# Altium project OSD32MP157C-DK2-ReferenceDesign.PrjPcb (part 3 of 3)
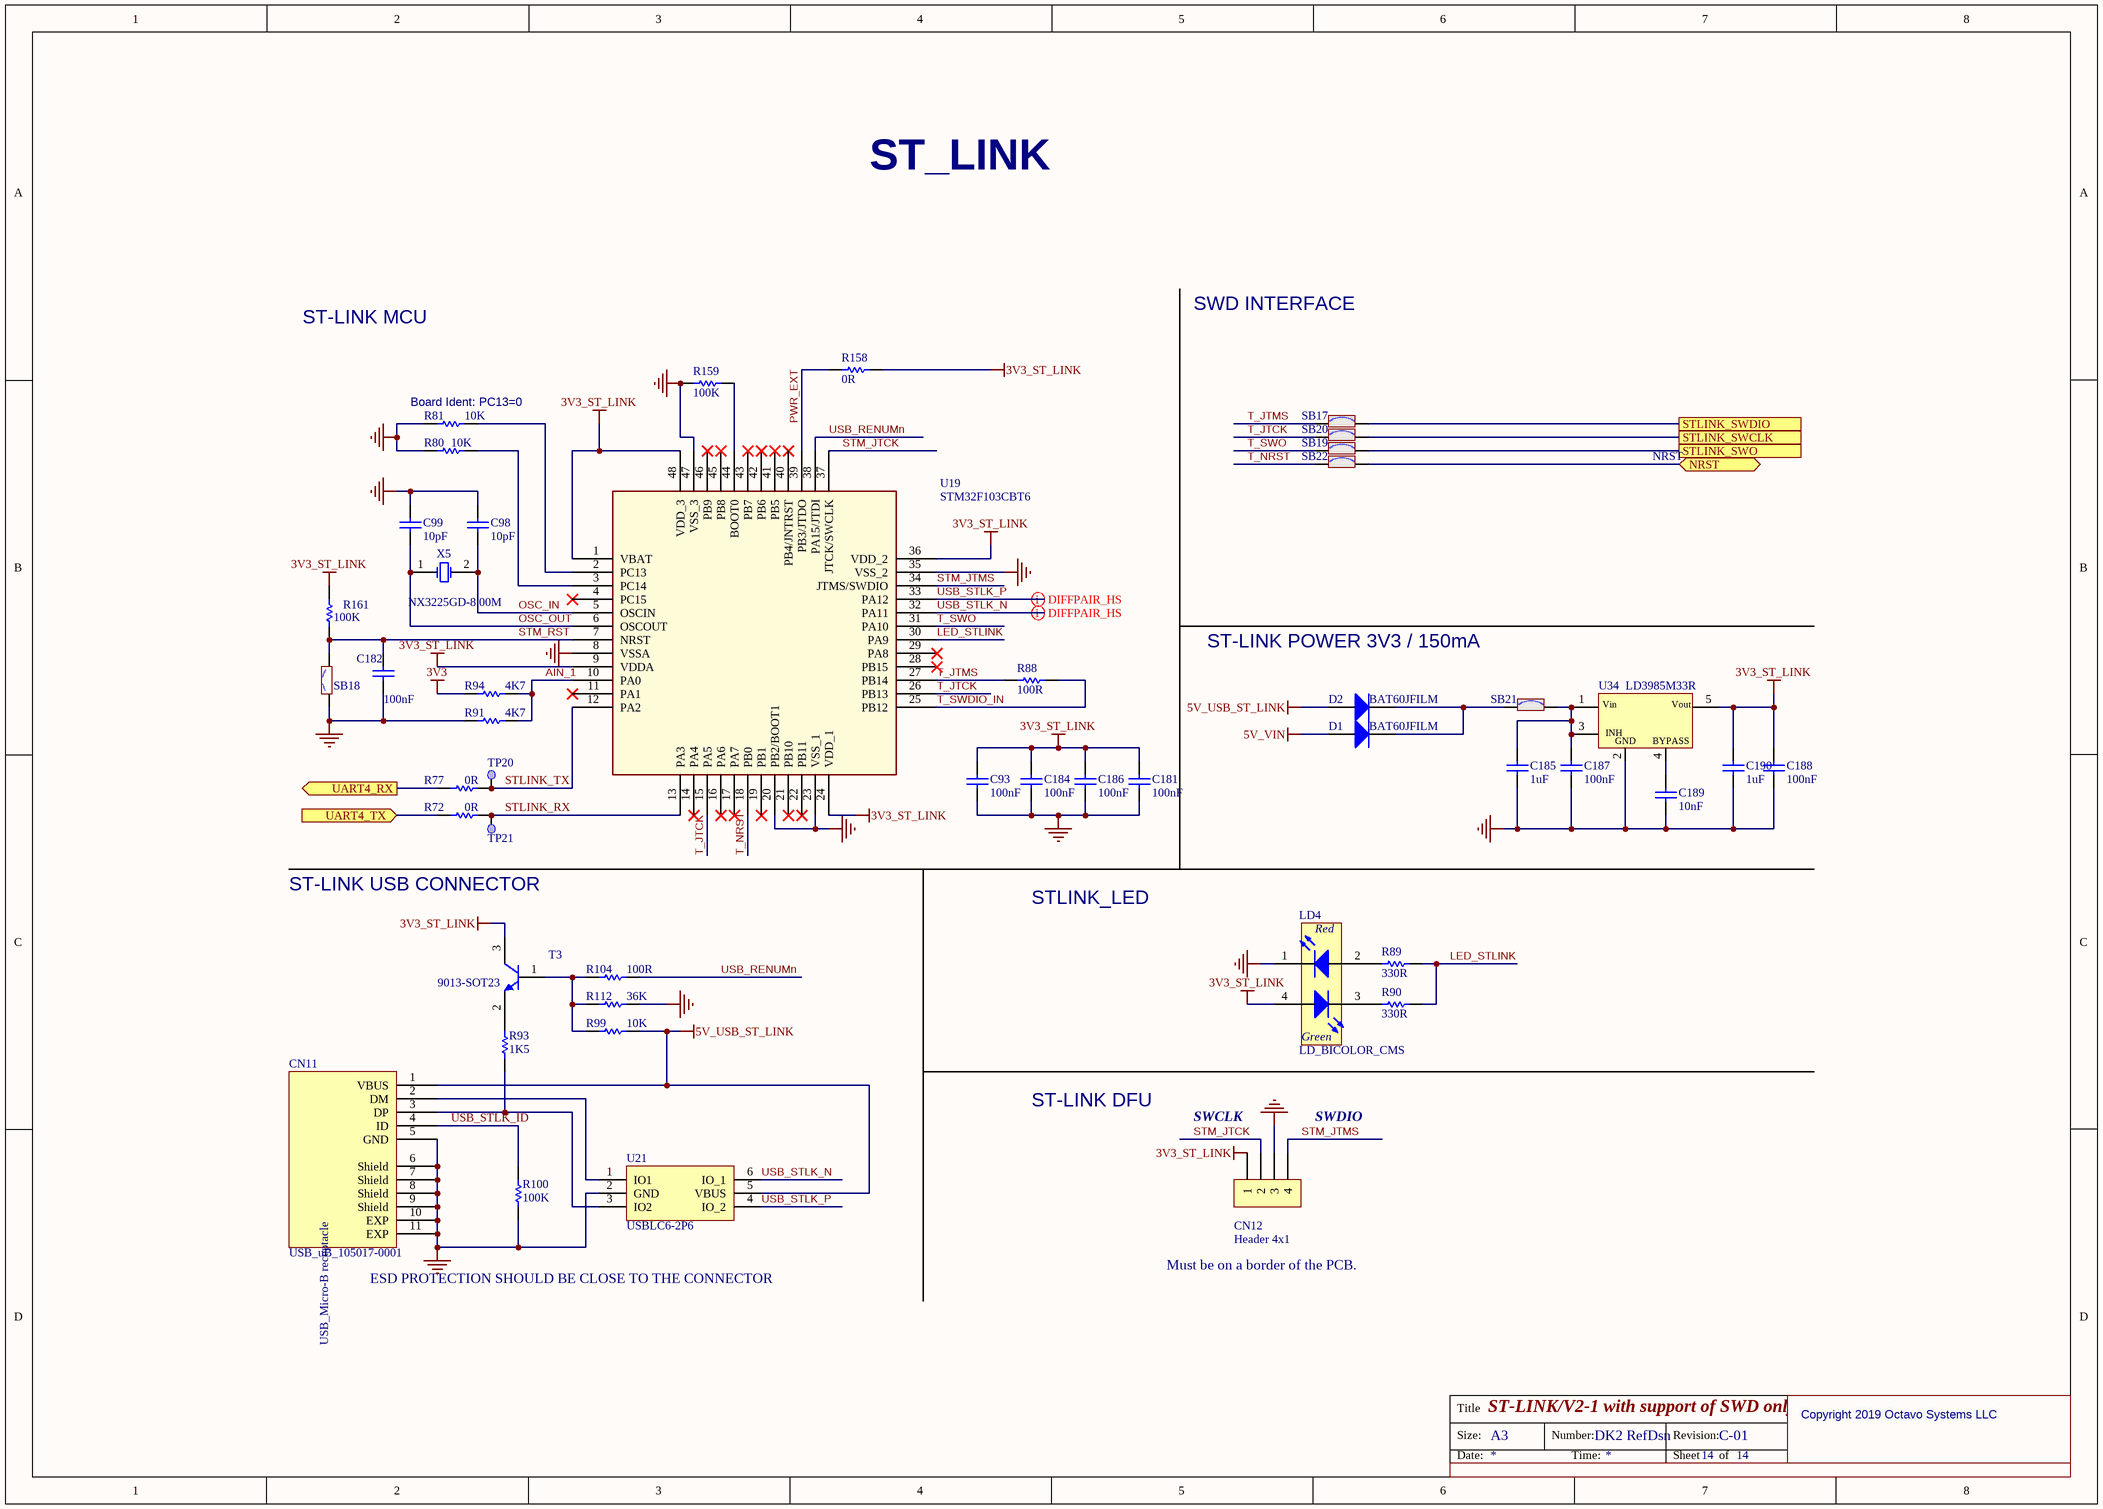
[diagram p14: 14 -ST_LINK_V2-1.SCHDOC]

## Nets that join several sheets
1V2_HDMI: 3 - Power_MPU (U13.H4), 8 - HDMI (5 pins)
1V8_AUDIO: 3 - Power_MPU (U13.J4), 6 - AUDIO (8 pins)
3V3: 2 - OSD32MP157C_18x18 (6 pins), 3 - Power_MPU (U13.H3 U13.J3), 5 - USB_Host_Hub&TypeC_DRP (18 pins), 6 - AUDIO (SB5.1), 7 - DSI_LCD (L7.1 R11.1), 9 - GPIO_&_Arduino_ Connectors (5 pins), 11 - Ethernet (L10.2 L11.2), 12 -  Peripherals (10 pins), 13 - WLAN_BLUETOOTH (10 pins), 14 -ST_LINK_V2-1 (R94.1)
3V3_HDMI: 3 - Power_MPU (U13.G4), 8 - HDMI (R154.2)
5V_VIN: 3 - Power_MPU (7 pins), 4 - PMIC (6 pins), 5 - USB_Host_Hub&TypeC_DRP (9 pins), 8 - HDMI (F1.1 R97.2 R98.2), 9 - GPIO_&_Arduino_ Connectors (CN2.2 CN2.4 R165.1 U23.1), 14 -ST_LINK_V2-1 (D1.1)
GND: 2 - OSD32MP157C_18x18 (9 pins), 3 - Power_MPU (72 pins), 4 - PMIC (20 pins), 5 - USB_Host_Hub&TypeC_DRP (74 pins), 6 - AUDIO (8 pins), 7 - DSI_LCD (18 pins), 8 - HDMI (36 pins), 9 - GPIO_&_Arduino_ Connectors (15 pins), 11 - Ethernet (34 pins), 12 -  Peripherals (20 pins), 13 - WLAN_BLUETOOTH (22 pins), 14 -ST_LINK_V2-1 (35 pins)
VDD: 2 - OSD32MP157C_18x18 (R5.1 R7.1), 3 - Power_MPU (10 pins), 12 -  Peripherals (R101.2 R102.2 R109.2)
VREF+: 3 - Power_MPU (R78.2 R79.2 U13.M2), 9 - GPIO_&_Arduino_ Connectors (C1.2 R4.2)
ARD_A0: 2 - OSD32MP157C_18x18 (U13.L1), 9 - GPIO_&_Arduino_ Connectors (CN17.1)
ARD_A1: 2 - OSD32MP157C_18x18 (U13.L2), 9 - GPIO_&_Arduino_ Connectors (CN17.2)
ARD_A2: 2 - OSD32MP157C_18x18 (U13.B10), 9 - GPIO_&_Arduino_ Connectors (CN17.3)
ARD_A3: 2 - OSD32MP157C_18x18 (U13.A10), 9 - GPIO_&_Arduino_ Connectors (CN17.4)
ARD_A4: 2 - OSD32MP157C_18x18 (U13.B6), 9 - GPIO_&_Arduino_ Connectors (SB24.1)
ARD_A5: 2 - OSD32MP157C_18x18 (U13.C11), 9 - GPIO_&_Arduino_ Connectors (SB26.1)
ARD_D0: 2 - OSD32MP157C_18x18 (U13.D17), 9 - GPIO_&_Arduino_ Connectors (CN14.1)
ARD_D1: 2 - OSD32MP157C_18x18 (U13.D18), 9 - GPIO_&_Arduino_ Connectors (CN14.2)
ARD_D2: 2 - OSD32MP157C_18x18 (U13.T7), 9 - GPIO_&_Arduino_ Connectors (CN14.3)
ARD_D3: 2 - OSD32MP157C_18x18 (U13.C3), 9 - GPIO_&_Arduino_ Connectors (CN14.4)
ARD_D4: 2 - OSD32MP157C_18x18 (U13.E17), 9 - GPIO_&_Arduino_ Connectors (CN14.5)
ARD_D5: 2 - OSD32MP157C_18x18 (U13.A2), 9 - GPIO_&_Arduino_ Connectors (CN14.6)
ARD_D6: 2 - OSD32MP157C_18x18 (U13.E16), 9 - GPIO_&_Arduino_ Connectors (CN14.7)
ARD_D7: 2 - OSD32MP157C_18x18 (U13.U11), 9 - GPIO_&_Arduino_ Connectors (CN14.8)
ARD_D8: 2 - OSD32MP157C_18x18 (U13.C9), 9 - GPIO_&_Arduino_ Connectors (CN13.1)
ARD_D9: 2 - OSD32MP157C_18x18 (U13.B5), 9 - GPIO_&_Arduino_ Connectors (CN13.2)
ARD_D10: 2 - OSD32MP157C_18x18 (U13.V5), 9 - GPIO_&_Arduino_ Connectors (CN13.3)
ARD_D11: 2 - OSD32MP157C_18x18 (U13.V4), 9 - GPIO_&_Arduino_ Connectors (CN13.4)
ARD_D12: 2 - OSD32MP157C_18x18 (U13.T5), 9 - GPIO_&_Arduino_ Connectors (CN13.5)
ARD_D13: 2 - OSD32MP157C_18x18 (U13.U5), 9 - GPIO_&_Arduino_ Connectors (CN13.6 SB6.1)
ARD_D14: 2 - OSD32MP157C_18x18 (R166.2 U13.L18), 9 - GPIO_&_Arduino_ Connectors (CN2.3 CN13.9 SB23.1)
ARD_D15: 2 - OSD32MP157C_18x18 (R167.2 U13.L17), 9 - GPIO_&_Arduino_ Connectors (CN2.5 CN13.10 SB25.1)
AUDIO_RST: 2 - OSD32MP157C_18x18 (U13.M17), 6 - AUDIO (R84.2 U20.25)
BOOT0: 2 - OSD32MP157C_18x18 (U13.J6), 12 -  Peripherals (SW1.1)
BOOT1: 2 - OSD32MP157C_18x18 (U13.H6), 12 -  Peripherals (R82.2)
BOOT2: 2 - OSD32MP157C_18x18 (U13.G6), 12 -  Peripherals (SW1.2)
BT_DEV_WAKE: 2 - OSD32MP157C_18x18 (U13.D2), 13 - WLAN_BLUETOOTH (U8.39)
BT_HOST_WAKE: 2 - OSD32MP157C_18x18 (U13.T6), 13 - WLAN_BLUETOOTH (U8.38)
BT_PCM_CLK: 2 - OSD32MP157C_18x18 (U13.F1), 13 - WLAN_BLUETOOTH (U8.11)
BT_PCM_SDI: 2 - OSD32MP157C_18x18 (U13.F2), 13 - WLAN_BLUETOOTH (U8.10)
BT_PCM_SDO: 2 - OSD32MP157C_18x18 (U13.F3), 13 - WLAN_BLUETOOTH (U8.9)
BT_PCM_WS: 2 - OSD32MP157C_18x18 (U13.E1), 13 - WLAN_BLUETOOTH (U8.8)
BT_REG_ON: 2 - OSD32MP157C_18x18 (U13.D1), 13 - WLAN_BLUETOOTH (TP29.1 U8.14)
DSI_CK_N: 2 - OSD32MP157C_18x18 (U13.P16), 7 - DSI_LCD (CN4.9 CN4.10)
DSI_CK_P: 2 - OSD32MP157C_18x18 (U13.N16), 7 - DSI_LCD (CN4.11 CN4.12)
DSI_D0_N: 2 - OSD32MP157C_18x18 (U13.P18), 7 - DSI_LCD (CN4.15 CN4.16)
DSI_D0_P: 2 - OSD32MP157C_18x18 (U13.P17), 7 - DSI_LCD (CN4.17 CN4.18)
DSI_D1_N: 2 - OSD32MP157C_18x18 (U13.N18), 7 - DSI_LCD (CN4.3 CN4.4)
DSI_D1_P: 2 - OSD32MP157C_18x18 (U13.N17), 7 - DSI_LCD (CN4.5 CN4.6)
DSI_LCD_BL_CTRL: 2 - OSD32MP157C_18x18 (U13.T15), 7 - DSI_LCD (CN4.37 CN4.38)
DSI_LCD_INT: 2 - OSD32MP157C_18x18 (U13.T18), 7 - DSI_LCD (CN4.33 CN4.34)
DSI_RESET: 2 - OSD32MP157C_18x18 (U13.R17), 7 - DSI_LCD (CN4.39 CN4.40 R11.2)
DSI_TE: 2 - OSD32MP157C_18x18 (U13.R18), 7 - DSI_LCD (CN4.35 CN4.36)
ETH_CLK: 2 - OSD32MP157C_18x18 (U13.C17), 11 - Ethernet (R69.2)
ETH_CLK125: 2 - OSD32MP157C_18x18 (U13.C15), 11 - Ethernet (R153.1)
ETH_GTX_CLK: 2 - OSD32MP157C_18x18 (U13.B9), 11 - Ethernet (U18.20)
ETH_MDC: 2 - OSD32MP157C_18x18 (U13.B15), 11 - Ethernet (R76.1 U18.13)
ETH_MDINT: 2 - OSD32MP157C_18x18 (U13.B17), 11 - Ethernet (R65.1 U18.31)
ETH_MDIO: 2 - OSD32MP157C_18x18 (U13.A15), 11 - Ethernet (R75.1 U18.14)
ETH_NRST: 2 - OSD32MP157C_18x18 (R300.2 U13.C8), 11 - Ethernet (U18.12)
ETH_RX_CLK: 2 - OSD32MP157C_18x18 (U13.C16), 11 - Ethernet (R50.2 R58.1)
ETH_RX_DV: 2 - OSD32MP157C_18x18 (U13.A12), 11 - Ethernet (R51.2 R59.1)
ETH_RXD0: 2 - OSD32MP157C_18x18 (U13.B12), 11 - Ethernet (R52.1 R60.1)
ETH_RXD1: 2 - OSD32MP157C_18x18 (U13.C12), 11 - Ethernet (R53.1 R61.1)
ETH_RXD2: 2 - OSD32MP157C_18x18 (U13.A11), 11 - Ethernet (R54.2 R62.1)
ETH_RXD3: 2 - OSD32MP157C_18x18 (U13.B11), 11 - Ethernet (R55.1 R63.1)
ETH_TX_EN: 2 - OSD32MP157C_18x18 (U13.A9), 11 - Ethernet (U18.19)
ETH_TXD0: 2 - OSD32MP157C_18x18 (U13.B7), 11 - Ethernet (U18.18)
ETH_TXD1: 2 - OSD32MP157C_18x18 (U13.A7), 11 - Ethernet (U18.17)
ETH_TXD2: 2 - OSD32MP157C_18x18 (U13.C7), 11 - Ethernet (U18.16)
ETH_TXD3: 2 - OSD32MP157C_18x18 (U13.A6), 11 - Ethernet (U18.15)
EXP_GPIO4: 2 - OSD32MP157C_18x18 (TP19.1 U13.T17), 9 - GPIO_&_Arduino_ Connectors (CN2.7)
EXP_GPIO5: 2 - OSD32MP157C_18x18 (TP1.1 U13.A8), 9 - GPIO_&_Arduino_ Connectors (CN2.29)
EXP_GPIO6: 2 - OSD32MP157C_18x18 (U13.V2), 9 - GPIO_&_Arduino_ Connectors (CN2.31)
EXP_GPIO7: 2 - OSD32MP157C_18x18 (U13.C6), 9 - GPIO_&_Arduino_ Connectors (CN2.26)
EXP_GPIO8: 2 - OSD32MP157C_18x18 (U13.F18), 9 - GPIO_&_Arduino_ Connectors (CN2.24)
EXP_GPIO9: 2 - OSD32MP157C_18x18 (U13.G17), 9 - GPIO_&_Arduino_ Connectors (CN2.21)
EXP_GPIO10: 2 - OSD32MP157C_18x18 (U13.G18), 9 - GPIO_&_Arduino_ Connectors (CN2.19)
EXP_GPIO11: 2 - OSD32MP157C_18x18 (U13.G16), 9 - GPIO_&_Arduino_ Connectors (CN2.23)
EXP_GPIO12: 2 - OSD32MP157C_18x18 (U13.F17), 9 - GPIO_&_Arduino_ Connectors (CN2.32)
EXP_GPIO13: 2 - OSD32MP157C_18x18 (U13.R16), 9 - GPIO_&_Arduino_ Connectors (CN2.33)
EXP_GPIO14: 2 - OSD32MP157C_18x18 (U13.A13), 9 - GPIO_&_Arduino_ Connectors (CN2.8)
EXP_GPIO15: 2 - OSD32MP157C_18x18 (U13.B14), 9 - GPIO_&_Arduino_ Connectors (CN2.10)
EXP_GPIO16: 2 - OSD32MP157C_18x18 (U13.A14), 9 - GPIO_&_Arduino_ Connectors (CN2.36)
EXP_GPIO17: 2 - OSD32MP157C_18x18 (U13.D16), 9 - GPIO_&_Arduino_ Connectors (CN2.11)
EXP_GPIO18: 2 - OSD32MP157C_18x18 (SB14.1), 9 - GPIO_&_Arduino_ Connectors (CN2.12)
EXP_GPIO19: 2 - OSD32MP157C_18x18 (SB16.1), 9 - GPIO_&_Arduino_ Connectors (CN2.35)
EXP_GPIO20: 2 - OSD32MP157C_18x18 (SB15.1), 9 - GPIO_&_Arduino_ Connectors (CN2.38)
EXP_GPIO21: 2 - OSD32MP157C_18x18 (SB13.1), 9 - GPIO_&_Arduino_ Connectors (CN2.40)
EXP_GPIO22: 2 - OSD32MP157C_18x18 (U13.V9), 9 - GPIO_&_Arduino_ Connectors (CN2.15)
EXP_GPIO23: 2 - OSD32MP157C_18x18 (U13.V8), 9 - GPIO_&_Arduino_ Connectors (CN2.16)
EXP_GPIO24: 2 - OSD32MP157C_18x18 (U13.U8), 9 - GPIO_&_Arduino_ Connectors (CN2.18)
EXP_GPIO25: 2 - OSD32MP157C_18x18 (U13.V7), 9 - GPIO_&_Arduino_ Connectors (CN2.22)
EXP_GPIO26: 2 - OSD32MP157C_18x18 (U13.T8), 9 - GPIO_&_Arduino_ Connectors (CN2.37)
EXP_GPIO27: 2 - OSD32MP157C_18x18 (U13.U9), 9 - GPIO_&_Arduino_ Connectors (CN2.13)
HDMI_CEC: 2 - OSD32MP157C_18x18 (U13.H18), 8 - HDMI (U14.50)
HDMI_INT: 2 - OSD32MP157C_18x18 (U13.B8), 8 - HDMI (U14.52)
HDMI_NRST: 2 - OSD32MP157C_18x18 (R40.2 U13.L16), 8 - HDMI (U14.51)
I2C1_SCL: 2 - OSD32MP157C_18x18 (R1.2 U13.F16), 5 - USB_Host_Hub&TypeC_DRP (SB8.1), 6 - AUDIO (R85.2), 7 - DSI_LCD (CN4.21 CN4.22), 8 - HDMI (U14.1), 9 - GPIO_&_Arduino_ Connectors (CN2.28)
I2C1_SDA: 2 - OSD32MP157C_18x18 (R2.2 U13.C10), 5 - USB_Host_Hub&TypeC_DRP (SB7.1), 6 - AUDIO (R86.2), 7 - DSI_LCD (CN4.23 CN4.24), 8 - HDMI (U14.2), 9 - GPIO_&_Arduino_ Connectors (CN2.27)
I2C4_SCL: 2 - OSD32MP157C_18x18 (R5.2 U13.E2), 5 - USB_Host_Hub&TypeC_DRP (U12.7)
I2C4_SDA: 2 - OSD32MP157C_18x18 (R7.2 U13.E3), 5 - USB_Host_Hub&TypeC_DRP (U12.8)
I2S2_CK: 2 - OSD32MP157C_18x18 (U13.U12), 8 - HDMI (U14.45)
I2S2_SDO: 2 - OSD32MP157C_18x18 (U13.R3), 8 - HDMI (U14.41)
I2S2_WS: 2 - OSD32MP157C_18x18 (U13.U13), 8 - HDMI (U14.44)
JTDO_TRACESWO: 2 - OSD32MP157C_18x18 (TP8.1 U13.R12), 14 -ST_LINK_V2-1 (SB19.2)
LED_B: 2 - OSD32MP157C_18x18 (U13.E18), 12 -  Peripherals (R108.1)
LED_Y: 2 - OSD32MP157C_18x18 (U13.C5), 12 -  Peripherals (R107.1)
LPO_32: 2 - OSD32MP157C_18x18 (U13.C1), 13 - WLAN_BLUETOOTH (TP26.1 U8.37)
LTDC_B0: 2 - OSD32MP157C_18x18 (U13.B1), 8 - HDMI (U14.32)
LTDC_B1: 2 - OSD32MP157C_18x18 (U13.A4), 8 - HDMI (U14.31)
LTDC_B2: 2 - OSD32MP157C_18x18 (U13.C18), 8 - HDMI (U14.30)
LTDC_B3: 2 - OSD32MP157C_18x18 (U13.V6), 8 - HDMI (U14.29)
LTDC_B4: 2 - OSD32MP157C_18x18 (U13.P1), 8 - HDMI (U14.28)
LTDC_B5: 2 - OSD32MP157C_18x18 (U13.A5), 8 - HDMI (U14.27)
LTDC_B6: 2 - OSD32MP157C_18x18 (U13.T13), 8 - HDMI (U14.25)
LTDC_B7: 2 - OSD32MP157C_18x18 (U13.B2), 8 - HDMI (U14.24)
LTDC_CLK: 2 - OSD32MP157C_18x18 (U13.H17), 8 - HDMI (U14.22)
LTDC_DE: 2 - OSD32MP157C_18x18 (U13.H16), 8 - HDMI (U14.33)
LTDC_G0: 2 - OSD32MP157C_18x18 (U13.V15), 8 - HDMI (U14.23)
LTDC_G1: 2 - OSD32MP157C_18x18 (U13.T9), 8 - HDMI (U14.20)
LTDC_G2: 2 - OSD32MP157C_18x18 (U13.U1), 8 - HDMI (U14.19)
LTDC_G3: 2 - OSD32MP157C_18x18 (U13.T1), 8 - HDMI (U14.18)
LTDC_G4: 2 - OSD32MP157C_18x18 (U13.T2), 8 - HDMI (U14.17)
LTDC_G5: 2 - OSD32MP157C_18x18 (U13.T3), 8 - HDMI (U14.16)
LTDC_G6: 2 - OSD32MP157C_18x18 (U13.R1), 8 - HDMI (U14.15)
LTDC_G7: 2 - OSD32MP157C_18x18 (U13.R2), 8 - HDMI (U14.14)
LTDC_HSYNC: 2 - OSD32MP157C_18x18 (U13.B4), 8 - HDMI (U14.34)
LTDC_R0: 2 - OSD32MP157C_18x18 (U13.B13), 8 - HDMI (U14.13)
LTDC_R1: 2 - OSD32MP157C_18x18 (U13.C13), 8 - HDMI (U14.11)
LTDC_R2: 2 - OSD32MP157C_18x18 (U13.T4), 8 - HDMI (U14.10)
LTDC_R3: 2 - OSD32MP157C_18x18 (U13.V3), 8 - HDMI (U14.9)
LTDC_R4: 2 - OSD32MP157C_18x18 (U13.U3), 8 - HDMI (U14.8)
LTDC_R5: 2 - OSD32MP157C_18x18 (U13.A17), 8 - HDMI (U14.7)
LTDC_R6: 2 - OSD32MP157C_18x18 (U13.U2), 8 - HDMI (U14.6)
LTDC_R7: 2 - OSD32MP157C_18x18 (U13.U4), 8 - HDMI (U14.4)
LTDC_VSYNC: 2 - OSD32MP157C_18x18 (U13.C2), 8 - HDMI (U14.35)
NRST: 2 - OSD32MP157C_18x18 (U13.M3), 9 - GPIO_&_Arduino_ Connectors (CN16.3), 12 -  Peripherals (5 pins), 14 -ST_LINK_V2-1 (SB22.2)
PA13: 2 - OSD32MP157C_18x18 (U13.A3), 12 -  Peripherals (B4.1 B4.2 LD6.2)
PA14: 2 - OSD32MP157C_18x18 (U13.B3), 12 -  Peripherals (B3.1 B3.2 LD5.2)
SAI2_FSA: 2 - OSD32MP157C_18x18 (SB1.1), 6 - AUDIO (U20.1)
SAI2_MCLKA: 2 - OSD32MP157C_18x18 (U13.U7), 6 - AUDIO (U20.30)
SAI2_SCKA: 2 - OSD32MP157C_18x18 (SB3.1), 6 - AUDIO (U20.31)
SAI2_SDA: 2 - OSD32MP157C_18x18 (SB2.1), 6 - AUDIO (U20.32)
SAI2_SDB: 2 - OSD32MP157C_18x18 (SB4.1), 6 - AUDIO (U20.29)
SDMMC1_CK: 2 - OSD32MP157C_18x18 (U13.V17), 12 -  Peripherals (CN15.5 R19.1 U10.2 U10.9)
SDMMC1_CMD: 2 - OSD32MP157C_18x18 (U13.U18), 12 -  Peripherals (CN15.3 R25.1 U10.1 U10.10)
SDMMC1_D0: 2 - OSD32MP157C_18x18 (U13.T16), 12 -  Peripherals (CN15.7 R16.1 U26.4 U26.7)
SDMMC1_D1: 2 - OSD32MP157C_18x18 (U13.U16), 12 -  Peripherals (CN15.8 R14.1 U26.5 U26.6)
SDMMC1_D2: 2 - OSD32MP157C_18x18 (U13.V16), 12 -  Peripherals (CN15.1 R33.1 U26.1 U26.10)
SDMMC1_D3: 2 - OSD32MP157C_18x18 (U13.U17), 12 -  Peripherals (CN15.2 R28.1 U26.2 U26.9)
SDMMC2_CK: 2 - OSD32MP157C_18x18 (U13.T12), 13 - WLAN_BLUETOOTH (TP25.1 U8.20)
SDMMC2_CMD: 2 - OSD32MP157C_18x18 (U13.U15), 13 - WLAN_BLUETOOTH (R26.2 U8.22)
SDMMC2_D0: 2 - OSD32MP157C_18x18 (U13.T14), 13 - WLAN_BLUETOOTH (R22.2 U8.24)
SDMMC2_D1: 2 - OSD32MP157C_18x18 (U13.V13), 13 - WLAN_BLUETOOTH (R17.2 U8.26)
SDMMC2_D2: 2 - OSD32MP157C_18x18 (U13.V14), 13 - WLAN_BLUETOOTH (R27.2 U8.23)
SDMMC2_D3: 2 - OSD32MP157C_18x18 (U13.U14), 13 - WLAN_BLUETOOTH (R20.2 U8.25)
STLINK_SWCLK: 2 - OSD32MP157C_18x18 (TP5.1 U13.R15), 14 -ST_LINK_V2-1 (SB20.2)
STLINK_SWDIO: 2 - OSD32MP157C_18x18 (TP3.1 U13.R14), 14 -ST_LINK_V2-1 (SB17.2)
STUSB1600_IRQOUTn: 2 - OSD32MP157C_18x18 (U13.C4), 5 - USB_Host_Hub&TypeC_DRP (U12.9)
UART4_RX: 2 - OSD32MP157C_18x18 (U13.M18), 14 -ST_LINK_V2-1 (R77.2)
UART4_TX: 2 - OSD32MP157C_18x18 (U13.C14), 14 -ST_LINK_V2-1 (R72.1)
USART2_CTS: 2 - OSD32MP157C_18x18 (U13.T11), 13 - WLAN_BLUETOOTH (U8.5)
USART2_RTS: 2 - OSD32MP157C_18x18 (U13.V10), 13 - WLAN_BLUETOOTH (U8.4)
USART2_RX: 2 - OSD32MP157C_18x18 (U13.T10), 13 - WLAN_BLUETOOTH (TP27.1 U8.3)
USART2_TX: 2 - OSD32MP157C_18x18 (U13.U10), 13 - WLAN_BLUETOOTH (TP28.1 U8.2)
USB1_N: 2 - OSD32MP157C_18x18 (U13.K18), 5 - USB_Host_Hub&TypeC_DRP (U7.30)
USB1_P: 2 - OSD32MP157C_18x18 (U13.K17), 5 - USB_Host_Hub&TypeC_DRP (U7.31)
USB2_N: 2 - OSD32MP157C_18x18 (U13.J17), 5 - USB_Host_Hub&TypeC_DRP (U29.2)
USB2_P: 2 - OSD32MP157C_18x18 (U13.J18), 5 - USB_Host_Hub&TypeC_DRP (U29.1)
USB_PWR_CC1: 2 - OSD32MP157C_18x18 (U13.B16), 4 - PMIC (R49.2)
USB_PWR_CC2: 2 - OSD32MP157C_18x18 (U13.A16), 4 - PMIC (R56.2)
uSD_DETECT: 2 - OSD32MP157C_18x18 (U13.V12), 12 -  Peripherals (R13.1)
WL_HOST_WAKE: 2 - OSD32MP157C_18x18 (U13.V11), 13 - WLAN_BLUETOOTH (U8.27)
WL_REG_ON: 2 - OSD32MP157C_18x18 (U13.U6), 13 - WLAN_BLUETOOTH (TP24.1 U8.28)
